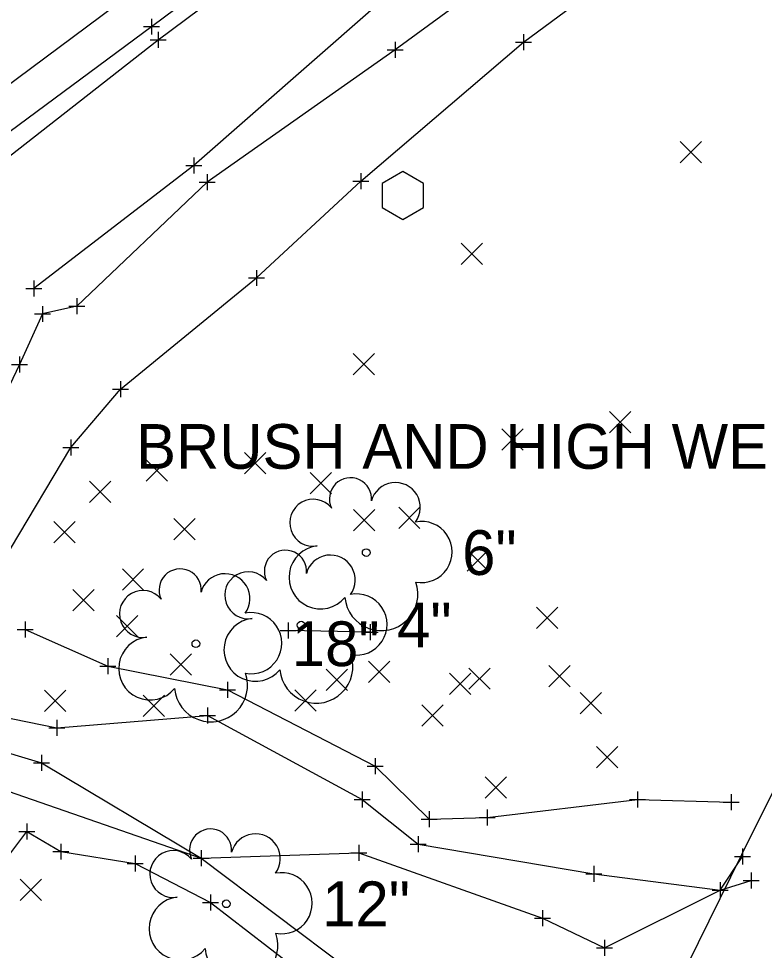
# Model space of a CAD drawing. Extents: x 120332 to 120776, y 463407 to 463745.
# Drawn here: x 120496.2 to 120542.9, y 463500.9 to 463559.2 of the extents above; entities that cross this region are included whole.
import ezdxf

# ---------------------------------------------------------------- set-up
doc = ezdxf.new("R2010")
doc.units = 0
for name, color, linetype in [('_CIVIL_CONSTRUCTION', 7, 'Continuous'), ('Default', 7, 'Continuous'), ('GE_X_Alignment', 7, 'Continuous'), ('GE_X_Alignment_100_Bearings', 7, 'Continuous'), ('GE_X_Alignment_100_Cardinal_Points', 7, 'Continuous'), ('GE_X_Alignment_100_Stations', 7, 'Continuous'), ('SC_Scratch1', 7, 'Continuous'), ('SV_P_Control_Cells_Set', 7, 'Continuous'), ('SV_X_Break_Lines', 7, 'Continuous'), ('SV_X_Mon_Cells_Found', 7, 'Continuous'), ('SV_X_Random_Point', 7, 'Continuous'), ('SV_X_Terrain_Boundary', 7, 'Continuous'), ('VG_X_Text', 7, 'Continuous')]:
    doc.layers.add(name, color=color, linetype=linetype)

msp = doc.modelspace()

# ---------------------------------------------------------------- linework, layer by layer
at = {"layer": '_CIVIL_CONSTRUCTION'}
for centre in [(120517.957, 463525.809), (120513.89, 463521.273), (120507.303, 463520.103), (120509.204, 463503.826)]:
    msp.add_circle(centre, 0.24, dxfattribs=at)
for centre, radius, start, end in [((120516.973, 463529.176), 1.317, 354.0047, 205.97412), ((120519.783, 463528.638), 1.553, 323.82996, 165.0376), ((120514.647, 463527.673), 1.471, 39.06254, 279.54124), ((120521.417, 463525.845), 1.915, 259.14531, 101.45961), ((120512.906, 463524.64), 1.317, 354.0047, 205.97412), ((120515.103, 463524.26), 1.974, 96.17219, 320.57371), ((120515.716, 463524.102), 1.553, 323.82996, 165.0376), ((120506.319, 463523.471), 1.317, 354.0047, 205.97412), ((120509.129, 463522.932), 1.553, 323.82996, 165.0376), ((120510.58, 463523.137), 1.471, 39.06254, 279.54124), ((120518.903, 463523.203), 2.284, 184.94757, 19.45715), ((120503.994, 463521.967), 1.471, 39.06254, 279.54124), ((120517.35, 463521.309), 1.915, 259.14531, 101.45961), ((120510.763, 463520.139), 1.915, 259.14531, 101.45961), ((120511.036, 463519.724), 1.974, 96.17219, 320.57371), ((120504.45, 463518.555), 1.974, 96.17219, 320.57371), ((120514.836, 463518.668), 2.284, 184.94757, 19.45715), ((120508.25, 463517.498), 2.284, 184.94757, 19.45715), ((120508.221, 463507.193), 1.317, 354.0047, 205.97412), ((120511.031, 463506.655), 1.553, 323.82996, 165.0376), ((120505.895, 463505.69), 1.471, 39.06254, 279.54124), ((120512.665, 463503.862), 1.915, 259.14531, 101.45961), ((120506.351, 463502.277), 1.974, 96.17219, 320.57371), ((120510.151, 463501.22), 2.284, 184.94757, 19.45715)]:
    msp.add_arc(centre, radius, start, end, dxfattribs=at)
at = {"layer": 'GE_X_Alignment'}
msp.add_lwpolyline([(120400.783, 463479.739), (120442.737, 463510.894), (120464.41, 463527.268), (120481.243, 463539.36), (120504.939, 463557.897), (120520.741, 463569.694), (120562.769, 463600.781)], dxfattribs=at)
at = {"layer": 'GE_X_Alignment_100_Bearings'}
msp.add_lwpolyline([(120400.107, 463480.542), (120441.635, 463511.608), (120463.868, 463528.172), (120480.156, 463540.694), (120504.522, 463558.726), (120520.212, 463570.416), (120561.992, 463601.903)], dxfattribs=at)
at = {"layer": 'GE_X_Alignment_100_Cardinal_Points'}
msp.add_lwpolyline([(120399.179, 463482.462), (120440.008, 463513.656), (120462.571, 463530.317), (120478.529, 463542.396), (120503.143, 463560.741), (120518.65, 463572.527), (120560.392, 463604.032)], dxfattribs=at)
at = {"layer": 'GE_X_Alignment_100_Stations'}
msp.add_lwpolyline([(120399.179, 463482.462), (120440.008, 463513.656), (120462.571, 463530.317), (120478.529, 463542.396), (120503.143, 463560.741), (120518.65, 463572.527), (120560.392, 463604.032)], dxfattribs=at)
at = {"layer": 'SC_Scratch1'}
msp.add_lwpolyline([(120518.952, 463547.405), (120520.25, 463546.655), (120521.549, 463547.405), (120521.549, 463548.905), (120520.25, 463549.655), (120518.952, 463548.905), (120518.952, 463547.405)], dxfattribs=at)
at = {"layer": 'SV_P_Control_Cells_Set'}
for p, q in [((120537.586, 463550.212), (120538.92, 463551.547)), ((120537.586, 463551.547), (120538.92, 463550.212)), ((120523.892, 463543.831), (120525.226, 463545.166)), ((120523.892, 463545.166), (120525.226, 463543.831)), ((120517.135, 463536.929), (120518.468, 463538.264)), ((120517.135, 463538.264), (120518.468, 463536.929)), ((120533.183, 463533.299), (120534.516, 463534.634)), ((120533.183, 463534.634), (120534.516, 463533.299)), ((120526.436, 463532.209), (120527.769, 463533.544)), ((120526.436, 463533.544), (120527.769, 463532.209)), ((120510.343, 463530.737), (120511.676, 463532.072)), ((120510.343, 463532.072), (120511.676, 463530.737)), ((120504.199, 463530.278), (120505.533, 463531.613)), ((120504.199, 463531.613), (120505.533, 463530.278)), ((120514.445, 463529.476), (120515.778, 463530.811)), ((120514.445, 463530.811), (120515.778, 463529.476)), ((120500.655, 463528.952), (120501.988, 463530.287)), ((120500.655, 463530.287), (120501.988, 463528.952)), ((120517.168, 463527.161), (120518.501, 463528.496)), ((120517.168, 463528.496), (120518.501, 463527.161)), ((120519.988, 463527.315), (120521.322, 463528.65)), ((120519.988, 463528.65), (120521.322, 463527.315)), ((120498.428, 463526.409), (120499.761, 463527.744)), ((120498.428, 463527.744), (120499.761, 463526.409)), ((120505.927, 463526.603), (120507.26, 463527.938)), ((120505.927, 463527.938), (120507.26, 463526.603)), ((120524.276, 463524.64), (120525.609, 463525.975)), ((120524.276, 463525.975), (120525.609, 463524.64)), ((120502.705, 463523.461), (120504.038, 463524.796)), ((120502.705, 463524.796), (120504.038, 463523.461)), ((120499.617, 463522.161), (120500.95, 463523.496)), ((120499.617, 463523.496), (120500.95, 463522.161)), ((120502.34, 463520.542), (120503.673, 463521.878)), ((120502.34, 463521.878), (120503.673, 463520.542)), ((120528.6, 463521.065), (120529.934, 463522.4)), ((120528.6, 463522.4), (120529.934, 463521.065)), ((120505.7, 463518.142), (120507.034, 463519.477)), ((120505.7, 463519.477), (120507.034, 463518.142)), ((120518.107, 463517.673), (120519.441, 463519.008)), ((120518.107, 463519.008), (120519.441, 463517.673)), ((120515.452, 463517.185), (120516.785, 463518.52)), ((120515.452, 463518.52), (120516.785, 463517.185)), ((120524.373, 463517.25), (120525.706, 463518.585)), ((120524.373, 463518.585), (120525.706, 463517.25)), ((120529.38, 463517.401), (120530.713, 463518.736)), ((120529.38, 463518.736), (120530.713, 463517.401)), ((120523.177, 463516.927), (120524.51, 463518.262)), ((120523.177, 463518.262), (120524.51, 463516.927)), ((120497.842, 463515.865), (120499.175, 463517.2)), ((120497.842, 463517.2), (120499.175, 463515.865)), ((120513.485, 463515.88), (120514.818, 463517.215)), ((120513.485, 463517.215), (120514.818, 463515.88)), ((120504.008, 463515.547), (120505.341, 463516.882)), ((120504.008, 463516.882), (120505.341, 463515.547)), ((120531.349, 463515.719), (120532.683, 463517.054)), ((120531.349, 463517.054), (120532.683, 463515.719)), ((120521.428, 463514.952), (120522.761, 463516.287)), ((120521.428, 463516.287), (120522.761, 463514.952)), ((120532.353, 463512.335), (120533.687, 463513.671)), ((120532.353, 463513.671), (120533.687, 463512.335)), ((120525.398, 463510.444), (120526.731, 463511.78)), ((120525.398, 463511.78), (120526.731, 463510.444)), ((120496.32, 463504.033), (120497.653, 463505.368)), ((120496.32, 463505.368), (120497.653, 463504.033))]:
    msp.add_line(p, q, dxfattribs=at)
at = {"layer": 'SV_X_Break_Lines'}
for points in [[(120567.678, 463595.39), (120558.067, 463588.439), (120544.552, 463579.145), (120532.466, 463569.34), (120518.243, 463559.73), (120507.17, 463550.04), (120497.161, 463542.332)], [(120484.313, 463524.856), (120483.774, 463521.539), (120485.522, 463520.173), (120488.907, 463519.672), (120491.187, 463520.013), (120493.725, 463522.168), (120495.711, 463526.051), (120499.479, 463532.381), (120502.593, 463536.029), (120511.09, 463542.995), (120517.622, 463549.058), (120527.801, 463557.76), (120570.164, 463589.063)], [(120491.483, 463530.93), (120492.828, 463527.087), (120490.35, 463523.556), (120488.68, 463520.51), (120485.5, 463522.358), (120482.999, 463520.302), (120485.375, 463517.49), (120491.257, 463516.335), (120498.603, 463514.836), (120508.041, 463515.603), (120517.701, 463510.345), (120521.213, 463507.551), (120532.191, 463505.703), (120540.092, 463504.676), (120541.486, 463506.795)], [(120496.633, 463521.003), (120501.798, 463518.702), (120509.285, 463517.221), (120518.525, 463512.435), (120521.899, 463509.117), (120525.528, 463509.234), (120534.929, 463510.353), (120540.776, 463510.185)], [(120518.206, 463520.837), (120513.067, 463520.935)], [(120493.021, 463511.745), (120507.644, 463506.679), (120516.926, 463499.666), (120527.888, 463499.377), (120537.634, 463500.119)], [(120488.527, 463488.372), (120495.533, 463493.15), (120492.87, 463497.881), (120495.086, 463498.049), (120494.515, 463505.436), (120496.729, 463508.352), (120498.855, 463507.09), (120503.514, 463506.356), (120508.21, 463503.911), (120515.351, 463498.402), (120522.141, 463496.552), (120536.706, 463497.244)]]:
    msp.add_lwpolyline(points, dxfattribs=at)
at = {"layer": 'SV_X_Mon_Cells_Found'}
for p, q in [((120504.522, 463559.226), (120504.522, 463558.226)), ((120504.022, 463558.726), (120505.022, 463558.726)), ((120504.522, 463558.726), (120504.522, 463558.726)), ((120504.939, 463558.397), (120504.939, 463557.397)), ((120527.801, 463558.26), (120527.801, 463557.26)), ((120504.439, 463557.897), (120505.439, 463557.897)), ((120504.939, 463557.897), (120504.939, 463557.897)), ((120519.767, 463557.783), (120519.767, 463556.783)), ((120527.301, 463557.76), (120528.301, 463557.76)), ((120527.801, 463557.76), (120527.801, 463557.76)), ((120519.267, 463557.283), (120520.267, 463557.283)), ((120519.767, 463557.283), (120519.767, 463557.283)), ((120507.17, 463550.54), (120507.17, 463549.54)), ((120506.67, 463550.04), (120507.67, 463550.04)), ((120507.17, 463550.04), (120507.17, 463550.04)), ((120508.017, 463549.489), (120508.017, 463548.489)), ((120517.622, 463549.558), (120517.622, 463548.558)), ((120507.517, 463548.989), (120508.517, 463548.989)), ((120508.017, 463548.989), (120508.017, 463548.989)), ((120517.122, 463549.058), (120518.122, 463549.058)), ((120517.622, 463549.058), (120517.622, 463549.058)), ((120511.09, 463543.495), (120511.09, 463542.495)), ((120510.59, 463542.995), (120511.59, 463542.995)), ((120511.09, 463542.995), (120511.09, 463542.995)), ((120496.661, 463542.332), (120497.661, 463542.332)), ((120497.161, 463542.832), (120497.161, 463541.832)), ((120497.161, 463542.332), (120497.161, 463542.332)), ((120499.859, 463541.728), (120499.859, 463540.728)), ((120497.713, 463541.242), (120497.713, 463540.242)), ((120499.359, 463541.228), (120500.359, 463541.228)), ((120499.859, 463541.228), (120499.859, 463541.228)), ((120497.213, 463540.742), (120498.213, 463540.742)), ((120497.713, 463540.742), (120497.713, 463540.742)), ((120496.273, 463538.079), (120496.273, 463537.079)), ((120495.773, 463537.579), (120496.773, 463537.579)), ((120496.273, 463537.579), (120496.273, 463537.579)), ((120502.593, 463536.529), (120502.593, 463535.529)), ((120502.093, 463536.029), (120503.093, 463536.029)), ((120502.593, 463536.029), (120502.593, 463536.029)), ((120498.979, 463532.381), (120499.979, 463532.381)), ((120499.479, 463532.881), (120499.479, 463531.881)), ((120499.479, 463532.381), (120499.479, 463532.381)), ((120496.633, 463521.503), (120496.633, 463520.503)), ((120513.067, 463521.435), (120513.067, 463520.435)), ((120518.206, 463521.337), (120518.206, 463520.337)), ((120496.133, 463521.003), (120497.133, 463521.003)), ((120496.633, 463521.003), (120496.633, 463521.003)), ((120512.567, 463520.935), (120513.567, 463520.935)), ((120513.067, 463520.935), (120513.067, 463520.935)), ((120517.706, 463520.837), (120518.706, 463520.837)), ((120518.206, 463520.837), (120518.206, 463520.837)), ((120501.798, 463519.202), (120501.798, 463518.202)), ((120501.298, 463518.702), (120502.298, 463518.702)), ((120501.798, 463518.702), (120501.798, 463518.702)), ((120508.785, 463517.221), (120509.785, 463517.221)), ((120509.285, 463517.721), (120509.285, 463516.721)), ((120509.285, 463517.221), (120509.285, 463517.221)), ((120508.041, 463516.103), (120508.041, 463515.103)), ((120507.541, 463515.603), (120508.541, 463515.603)), ((120508.041, 463515.603), (120508.041, 463515.603)), ((120498.603, 463515.336), (120498.603, 463514.336)), ((120498.103, 463514.836), (120499.103, 463514.836)), ((120498.603, 463514.836), (120498.603, 463514.836)), ((120497.651, 463513.153), (120497.651, 463512.153)), ((120497.151, 463512.653), (120498.151, 463512.653)), ((120497.651, 463512.653), (120497.651, 463512.653)), ((120518.525, 463512.935), (120518.525, 463511.935)), ((120518.025, 463512.435), (120519.025, 463512.435)), ((120518.525, 463512.435), (120518.525, 463512.435)), ((120517.701, 463510.845), (120517.701, 463509.845)), ((120534.929, 463510.853), (120534.929, 463509.853)), ((120517.201, 463510.345), (120518.201, 463510.345)), ((120517.701, 463510.345), (120517.701, 463510.345)), ((120534.429, 463510.353), (120535.429, 463510.353)), ((120534.929, 463510.353), (120534.929, 463510.353)), ((120540.776, 463510.685), (120540.776, 463509.685)), ((120521.899, 463509.617), (120521.899, 463508.617)), ((120525.528, 463509.734), (120525.528, 463508.734)), ((120540.276, 463510.185), (120541.276, 463510.185)), ((120540.776, 463510.185), (120540.776, 463510.185)), ((120521.399, 463509.117), (120522.399, 463509.117)), ((120521.899, 463509.117), (120521.899, 463509.117)), ((120525.028, 463509.234), (120526.028, 463509.234)), ((120525.528, 463509.234), (120525.528, 463509.234)), ((120496.729, 463508.852), (120496.729, 463507.852)), ((120496.229, 463508.352), (120497.229, 463508.352)), ((120496.729, 463508.352), (120496.729, 463508.352)), ((120521.213, 463508.051), (120521.213, 463507.051)), ((120498.855, 463507.59), (120498.855, 463506.59)), ((120517.493, 463507.507), (120517.493, 463506.507)), ((120520.713, 463507.551), (120521.713, 463507.551)), ((120521.213, 463507.551), (120521.213, 463507.551)), ((120541.486, 463507.295), (120541.486, 463506.295)), ((120498.355, 463507.09), (120499.355, 463507.09)), ((120498.855, 463507.09), (120498.855, 463507.09)), ((120503.514, 463506.856), (120503.514, 463505.856)), ((120507.644, 463507.179), (120507.644, 463506.179)), ((120516.993, 463507.007), (120517.993, 463507.007)), ((120517.493, 463507.007), (120517.493, 463507.007)), ((120540.986, 463506.795), (120541.986, 463506.795)), ((120541.486, 463506.795), (120541.486, 463506.795)), ((120503.014, 463506.356), (120504.014, 463506.356)), ((120503.514, 463506.356), (120503.514, 463506.356)), ((120507.144, 463506.679), (120508.144, 463506.679)), ((120507.644, 463506.679), (120507.644, 463506.679)), ((120532.191, 463506.203), (120532.191, 463505.203)), ((120531.691, 463505.703), (120532.691, 463505.703)), ((120532.191, 463505.703), (120532.191, 463505.703)), ((120542.032, 463505.79), (120542.032, 463504.79)), ((120540.092, 463505.176), (120540.092, 463504.176)), ((120541.532, 463505.29), (120542.532, 463505.29)), ((120542.032, 463505.29), (120542.032, 463505.29)), ((120508.21, 463504.411), (120508.21, 463503.411)), ((120539.592, 463504.676), (120540.592, 463504.676)), ((120540.092, 463504.676), (120540.092, 463504.676)), ((120507.71, 463503.911), (120508.71, 463503.911)), ((120508.21, 463503.911), (120508.21, 463503.911)), ((120528.983, 463503.436), (120528.983, 463502.436)), ((120528.483, 463502.936), (120529.483, 463502.936)), ((120528.983, 463502.936), (120528.983, 463502.936)), ((120532.862, 463501.571), (120532.862, 463500.571)), ((120532.362, 463501.071), (120533.362, 463501.071)), ((120532.862, 463501.071), (120532.862, 463501.071))]:
    msp.add_line(p, q, dxfattribs=at)
at = {"layer": 'SV_X_Random_Point'}
for points in [[(120569.138, 463593.998), (120559.049, 463586.735), (120546.371, 463576.844), (120533.287, 463567.164), (120519.767, 463557.283), (120508.017, 463548.989), (120499.859, 463541.228), (120497.713, 463540.742), (120496.273, 463537.579), (120495.203, 463535.345), (120494.829, 463534.161), (120492.198, 463532.352), (120491.301, 463530.313)], [(120488.788, 463529.47), (120488.698, 463527.586), (120484.743, 463527.628), (120481.024, 463525.133), (120481.04, 463520.059), (120484.744, 463515.904), (120490.842, 463514.686), (120497.651, 463512.653), (120507.644, 463506.679), (120517.493, 463507.007), (120528.983, 463502.936), (120532.862, 463501.071), (120540.092, 463504.676)], [(120540.092, 463504.676), (120542.032, 463505.29)]]:
    msp.add_lwpolyline(points, dxfattribs=at)
at = {"layer": 'SV_X_Terrain_Boundary'}
msp.add_lwpolyline([(120382.051, 463504.308), (120392.05, 463491.701), (120404.479, 463476.085), (120419.01, 463449.439), (120492.053, 463471.809), (120514.568, 463481.496), (120536.706, 463497.244), (120541.461, 463506.918), (120568.634, 463561.597), (120583.371, 463575.387), (120540.778, 463632.413), (120527.213, 463655.252), (120435.504, 463626.861), (120399.019, 463601.891), (120359.633, 463534.802), (120382.051, 463504.308)], dxfattribs=at)

# ---------------------------------------------------------------- texts
at = {"layer": 'Default'}
msp.add_text('BRUSH AND HIGH WEEDS', height=2.8, dxfattribs=at).set_placement((120503.566, 463531.053))
at = {"layer": 'VG_X_Text'}
for s, p in [('6"', (120523.957, 463524.409)), ('4"', (120519.89, 463519.873)), ('18"', (120513.303, 463518.703)), ('12"', (120515.204, 463502.426))]:
    msp.add_text(s, height=2.8, dxfattribs=at).set_placement(p)

doc.saveas('drawing.dxf')
